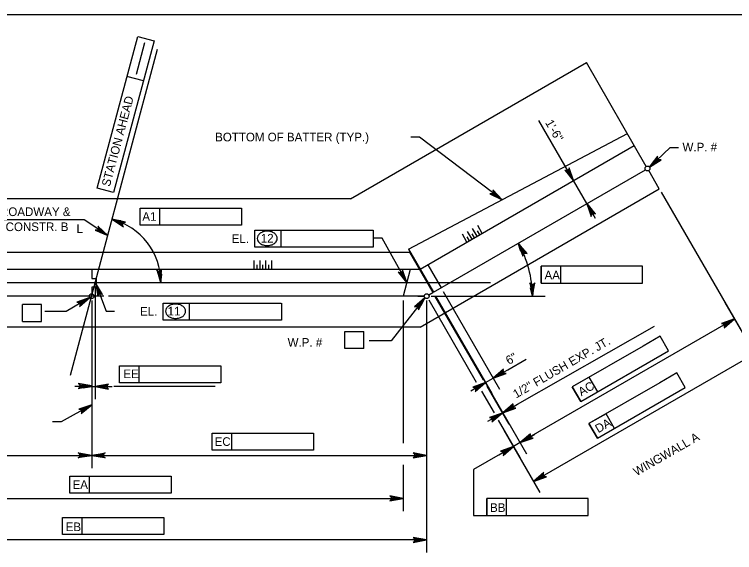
# Model space of a CAD drawing. Extents: x 638255 to 640306, y 296059 to 298435.
# Drawn here: x 638693.7 to 638944.1, y 297045.5 to 297232.5 of the extents above; entities that cross this region are included whole.
import ezdxf

# ---------------------------------------------------------------- set-up
doc = ezdxf.new("R2010")
doc.units = 0
for name, color, linetype in [('2', 7, 'Continuous'), ('Level 10', 7, 'Continuous'), ('Level 11', 7, 'Continuous'), ('Level 2', 7, 'Continuous'), ('Level 3', 7, 'Continuous')]:
    doc.layers.add(name, color=color, linetype=linetype)

msp = doc.modelspace()

# ---------------------------------------------------------------- linework, layer by layer
at = {"layer": '2'}
msp.add_line((638475.46, 297232.46), (639261.46, 297232.46), dxfattribs=at)
at = {"layer": 'Level 10'}
for p, q in [((638810.57, 297168.34), (638892.58, 297215.69)), ((638913.39, 297179.65), (638892.58, 297215.69)), ((638830.74, 297150.88), (638906.81, 297191.04)), ((638834.77, 297143.91), (638909.21, 297186.89)), ((638839.38, 297135.93), (638913.08, 297178.49)), ((638917.91, 297171.82), (638914.24, 297178.18)), ((638834.78, 297123.83), (638917.91, 297171.82)), ((638810.57, 297168.34), (638636.66, 297168.34)), ((638615.29, 297149.79), (638831.04, 297149.87)), ((638830.74, 297150.88), (638839.38, 297135.93)), ((638831.04, 297149.87), (638839.16, 297135.81)), ((638837.43, 297145.44), (638842.04, 297137.47)), ((638834.55, 297143.78), (638611.82, 297143.78)), ((638831.33, 297143.78), (638828.86, 297134.57)), ((638859.26, 297139.18), (638594.57, 297139.18)), ((638724.77, 297134.57), (638610.04, 297134.57)), ((638836.17, 297134.57), (638726.47, 297134.57)), ((638833.95, 297134.57), (638836.17, 297134.57)), ((638837.75, 297135), (638839.16, 297135.81)), ((638834.78, 297123.83), (638615.53, 297123.83))]:
    msp.add_line(p, q, dxfattribs=at)
at = {"layer": 'Level 11'}
msp.add_line((638713.23, 297107.11), (638743.43, 297220.39), dxfattribs=at)
at = {"layer": 'Level 2'}
for p, q in [((638856.37, 297156.38), (638854.79, 297159.11)), ((638852.82, 297154.33), (638851.25, 297157.06)), ((638854.59, 297155.36), (638853.02, 297158.09)), ((638855.48, 297155.87), (638854.67, 297157.27)), ((638851.05, 297153.31), (638849.47, 297156.04)), ((638851.94, 297153.82), (638851.13, 297155.22)), ((638853.71, 297154.84), (638852.9, 297156.25)), ((638777.06, 297143.78), (638777.06, 297146.94)), ((638779.11, 297143.78), (638779.11, 297146.94)), ((638781.15, 297143.78), (638781.15, 297146.94)), ((638783.2, 297143.78), (638783.2, 297146.94)), ((638778.08, 297143.78), (638778.08, 297145.4)), ((638780.13, 297143.78), (638780.13, 297145.4)), ((638782.18, 297143.78), (638782.18, 297145.4))]:
    msp.add_line(p, q, dxfattribs=at)
msp.add_lwpolyline([(638720.59, 297143.78), (638720.59, 297140.71), (638722.12, 297140.71), (638722.12, 297137.64), (638720.59, 297137.64), (638720.59, 297135.6)], dxfattribs=at)
at = {"layer": 'Level 3'}
for p, q in [((638722.47, 297172.11), (638736.59, 297224.82)), ((638736.59, 297224.82), (638742.29, 297223.3)), ((638742.29, 297223.3), (638728.16, 297170.59)), ((638736.14, 297211.74), (638739.07, 297222.66)), ((638738.55, 297209.36), (638732.86, 297210.89)), ((638888.1, 297174.7), (638875.99, 297195.65)), ((638834.54, 297189.85), (638831.55, 297189.85)), ((638863.24, 297168.04), (638834.54, 297189.85)), ((638914.53, 297179.36), (638921.68, 297186.2)), ((638921.68, 297186.2), (638924.63, 297186.2)), ((638892.7, 297166.72), (638888.1, 297174.7)), ((638728.16, 297170.59), (638722.47, 297172.11)), ((638918.6, 297170.64), (638946.21, 297122.8)), ((638892.7, 297166.72), (638895.65, 297161.62)), ((638737.4, 297165.15), (638744.23, 297165.15)), ((638737.4, 297159.26), (638737.4, 297165.15)), ((638744.23, 297159.26), (638744.23, 297165.15)), ((638744.23, 297165.15), (638772.63, 297165.15)), ((638772.63, 297165.15), (638772.63, 297159.26)), ((638717.98, 297161.05), (638683.42, 297161.05)), ((638726.16, 297155.59), (638717.98, 297161.05)), ((638772.63, 297159.26), (638737.4, 297159.26)), ((638777.26, 297157.48), (638786.41, 297157.48)), ((638777.26, 297151.59), (638777.26, 297157.48)), ((638786.41, 297151.59), (638786.41, 297157.48)), ((638786.41, 297157.48), (638818.39, 297157.48)), ((638818.39, 297157.48), (638818.39, 297151.59)), ((638821.56, 297154.7), (638818.62, 297154.7)), ((638830.11, 297139.25), (638821.56, 297154.7)), ((638818.39, 297151.59), (638777.26, 297151.59)), ((638876.81, 297144.93), (638876.81, 297139.03)), ((638905.21, 297144.93), (638876.81, 297144.93)), ((638883.64, 297144.93), (638876.81, 297144.93)), ((638876.81, 297139.03), (638876.81, 297144.93)), ((638883.64, 297139.03), (638883.64, 297144.93)), ((638912.04, 297144.93), (638905.21, 297144.93)), ((638912.04, 297139.03), (638912.04, 297144.93)), ((638721.9, 297139.18), (638725.57, 297129.37)), ((638876.81, 297139.03), (638912.04, 297139.03)), ((638721.83, 297137.64), (638721.83, 297098.72)), ((638719.91, 297134.05), (638711.71, 297129.18)), ((638836.41, 297133.96), (638824.75, 297119.07)), ((638838.55, 297134.57), (638878.2, 297134.57)), ((638839.92, 297134.48), (638856.66, 297105.49)), ((638840.14, 297134.6), (638871.77, 297079.82)), ((638840.14, 297134.6), (638865.77, 297090.23)), ((638840.14, 297134.6), (638859.72, 297100.69)), ((638842.8, 297136.14), (638862.38, 297102.23)), ((638696.52, 297125.74), (638696.52, 297131.64)), ((638703.1, 297131.64), (638696.52, 297131.64)), ((638703.1, 297125.74), (638703.1, 297131.64)), ((638720.59, 297133.04), (638720.59, 297074.8)), ((638745.39, 297126.26), (638745.39, 297132.15)), ((638745.39, 297132.15), (638754.55, 297132.15)), ((638754.55, 297126.26), (638754.55, 297132.15)), ((638754.55, 297132.15), (638786.42, 297132.15)), ((638786.52, 297132.15), (638786.52, 297126.26)), ((638828.91, 297133.04), (638828.91, 297083.47)), ((638837.02, 297133.04), (638837.02, 297074.8)), ((638837.79, 297133.24), (638854.27, 297104.68)), ((638940.68, 297132.38), (638953.19, 297110.73)), ((638711.71, 297129.18), (638704.35, 297129.18)), ((638725.57, 297129.37), (638728.51, 297129.37)), ((638944, 297126.63), (638869.56, 297083.65)), ((638696.52, 297125.74), (638703.1, 297125.74)), ((638786.52, 297126.26), (638745.39, 297126.26)), ((638868.66, 297097), (638916.2, 297124.14)), ((638808.63, 297122.31), (638815.21, 297122.31)), ((638808.63, 297116.42), (638808.63, 297122.31)), ((638815.21, 297116.42), (638815.21, 297122.31)), ((638824.75, 297119.07), (638816.99, 297119.07)), ((638918.18, 297120.65), (638912.26, 297117.23)), ((638921.13, 297115.54), (638918.18, 297120.65)), ((638912.26, 297117.23), (638887.67, 297103.03)), ((638815.21, 297116.42), (638808.63, 297116.42)), ((638950.98, 297114.55), (638874.17, 297070.21)), ((638890.62, 297097.93), (638921.13, 297115.54)), ((638865.27, 297109), (638871.65, 297112.68)), ((638730.22, 297110.38), (638737.05, 297110.38)), ((638730.22, 297104.49), (638730.22, 297110.38)), ((638737.05, 297104.49), (638737.05, 297110.38)), ((638737.05, 297110.38), (638765.45, 297110.38)), ((638765.45, 297110.38), (638765.45, 297104.49)), ((638862.72, 297107.53), (638865.27, 297109)), ((638893.58, 297106.45), (638887.67, 297103.03)), ((638896.53, 297101.34), (638893.58, 297106.45)), ((638923.97, 297107.89), (638918.06, 297104.48)), ((638926.92, 297102.79), (638923.97, 297107.89)), ((638765.45, 297104.49), (638730.22, 297104.49)), ((638857.51, 297104.52), (638860.17, 297106.06)), ((638918.06, 297104.48), (638893.46, 297090.28)), ((638717.64, 297103.14), (638714.7, 297103.14)), ((638720.59, 297103.14), (638721.83, 297103.14)), ((638724.77, 297103.14), (638727.72, 297103.14)), ((638763.49, 297103.14), (638728.24, 297103.14)), ((638854.96, 297103.05), (638852.41, 297101.57)), ((638856.06, 297101.59), (638860.45, 297093.99)), ((638857.92, 297103.3), (638865.54, 297090.1)), ((638887.67, 297103.03), (638890.62, 297097.93)), ((638890.61, 297097.93), (638887.67, 297103.03)), ((638896.41, 297085.17), (638926.92, 297102.79)), ((638720.59, 297096.82), (638709.96, 297090.87)), ((638866.11, 297095.53), (638868.66, 297097)), ((638837.02, 297094.09), (638837.02, 297045.45)), ((638863.33, 297093.93), (638863.55, 297094.06)), ((638860.78, 297092.45), (638858.23, 297090.98)), ((638861.89, 297091.5), (638869.41, 297078.46)), ((638899.38, 297093.69), (638893.46, 297090.28)), ((638902.32, 297088.59), (638899.38, 297093.69)), ((638709.96, 297090.87), (638707.01, 297090.87)), ((638893.46, 297090.28), (638896.41, 297085.17)), ((638896.41, 297085.17), (638893.46, 297090.28)), ((638762.5, 297086.94), (638769.33, 297086.94)), ((638762.5, 297081.05), (638762.5, 297086.94)), ((638769.33, 297081.05), (638769.33, 297086.94)), ((638769.33, 297086.94), (638797.73, 297086.94)), ((638797.73, 297086.94), (638797.73, 297081.05)), ((638863.89, 297088.04), (638876.38, 297066.39)), ((638872.11, 297085.12), (638874.67, 297086.6)), ((638867.2, 297082.29), (638853.36, 297074.3)), ((638869.56, 297083.65), (638867.2, 297082.29)), ((638609.2, 297079.23), (638720.59, 297079.23)), ((638720.59, 297079.23), (638837.02, 297079.23)), ((638797.73, 297081.05), (638762.5, 297081.05)), ((638864.65, 297080.81), (638862.1, 297079.34)), ((638828.91, 297076), (638828.91, 297059.84)), ((638853.36, 297074.3), (638853.36, 297058.37)), ((638712.98, 297071.98), (638719.81, 297071.98)), ((638712.98, 297066.08), (638712.98, 297071.98)), ((638719.81, 297066.08), (638719.81, 297071.98)), ((638719.81, 297071.98), (638748.21, 297071.98)), ((638748.21, 297071.98), (638748.21, 297066.08)), ((638612.27, 297064.26), (638828.91, 297064.26)), ((638748.21, 297066.08), (638712.98, 297066.08)), ((638857.96, 297064.27), (638857.96, 297058.37)), ((638886.36, 297064.27), (638857.96, 297064.27)), ((638864.79, 297064.27), (638857.96, 297064.27)), ((638857.96, 297058.37), (638857.96, 297064.27)), ((638864.79, 297058.37), (638864.79, 297064.27)), ((638893.19, 297064.27), (638886.36, 297064.27)), ((638893.19, 297058.37), (638893.19, 297064.27)), ((638710.46, 297057.59), (638717.29, 297057.59)), ((638710.46, 297051.7), (638710.46, 297057.59)), ((638717.29, 297051.7), (638717.29, 297057.59)), ((638717.29, 297057.59), (638745.7, 297057.59)), ((638745.7, 297057.59), (638745.7, 297051.7)), ((638853.36, 297058.37), (638857.96, 297058.37)), ((638857.96, 297058.37), (638893.19, 297058.37)), ((638745.7, 297051.7), (638710.46, 297051.7)), ((638837.02, 297049.88), (638609.2, 297049.88))]:
    msp.add_line(p, q, dxfattribs=at)
for points in [[(638914.53, 297179.36), (638918.5, 297181.95), (638918.07, 297181.88), (638917.72, 297181.98), (638917.46, 297182.16), (638917.29, 297182.43), (638917.2, 297182.78), (638917.29, 297183.21), (638914.53, 297179.36), (638917.2, 297182.78), (638917.29, 297182.43), (638914.53, 297179.36), (638917.46, 297182.16), (638917.72, 297181.98), (638914.53, 297179.36), (638918.07, 297181.88)], [(638888.1, 297174.7), (638886.53, 297179.16), (638886.49, 297178.73), (638886.31, 297178.41), (638886.07, 297178.21), (638885.77, 297178.1), (638885.41, 297178.1), (638885.01, 297178.29), (638888.1, 297174.7), (638885.41, 297178.1), (638885.77, 297178.1), (638888.1, 297174.7), (638886.07, 297178.21), (638886.31, 297178.41), (638888.1, 297174.7), (638886.49, 297178.73)], [(638863.24, 297168.04), (638860.07, 297171.55), (638860.2, 297171.14), (638860.16, 297170.78), (638860.01, 297170.5), (638859.78, 297170.28), (638859.45, 297170.14), (638859.01, 297170.16), (638863.24, 297168.04), (638859.45, 297170.14), (638859.78, 297170.28), (638863.24, 297168.04), (638860.01, 297170.5), (638860.16, 297170.78), (638863.24, 297168.04), (638860.2, 297171.14)], [(638892.7, 297166.72), (638894.27, 297162.26), (638894.31, 297162.69), (638894.49, 297163.01), (638894.73, 297163.21), (638895.03, 297163.32), (638895.39, 297163.32), (638895.78, 297163.13), (638892.7, 297166.72), (638895.39, 297163.32), (638895.03, 297163.32), (638892.7, 297166.72), (638894.73, 297163.21), (638894.49, 297163.01), (638892.7, 297166.72), (638894.31, 297162.69)], [(638727.68, 297161.27), (638731.63, 297158.67), (638731.4, 297159.04), (638731.35, 297159.4), (638731.42, 297159.71), (638731.59, 297159.97), (638731.88, 297160.19), (638732.31, 297160.28), (638727.68, 297161.27), (638731.88, 297160.19), (638731.59, 297159.97), (638727.68, 297161.27), (638731.42, 297159.71), (638731.35, 297159.4), (638727.68, 297161.27), (638731.4, 297159.04)], [(638726.16, 297155.59), (638722.77, 297158.9), (638722.93, 297158.49), (638722.91, 297158.13), (638722.79, 297157.84), (638722.57, 297157.61), (638722.24, 297157.46), (638721.8, 297157.45), (638726.16, 297155.59), (638722.24, 297157.46), (638722.57, 297157.61), (638726.16, 297155.59), (638722.79, 297157.84), (638722.91, 297158.13), (638726.16, 297155.59), (638722.93, 297158.49)], [(638868.86, 297152.96), (638870.43, 297148.49), (638870.46, 297148.93), (638870.64, 297149.24), (638870.88, 297149.44), (638871.18, 297149.55), (638871.54, 297149.55), (638871.94, 297149.36), (638868.86, 297152.96), (638871.54, 297149.55), (638871.18, 297149.55), (638868.86, 297152.96), (638870.88, 297149.44), (638870.64, 297149.24), (638868.86, 297152.96), (638870.46, 297148.93)], [(638744.68, 297139.16), (638744.9, 297143.89), (638744.71, 297143.5), (638744.42, 297143.27), (638744.12, 297143.17), (638743.8, 297143.18), (638743.47, 297143.33), (638743.18, 297143.65), (638744.68, 297139.16), (638743.47, 297143.33), (638743.8, 297143.18), (638744.68, 297139.16), (638744.12, 297143.17), (638744.42, 297143.27), (638744.68, 297139.16), (638744.71, 297143.5)], [(638830.11, 297139.25), (638828.62, 297143.74), (638828.58, 297143.31), (638828.4, 297142.99), (638828.15, 297142.79), (638827.85, 297142.69), (638827.49, 297142.7), (638827.1, 297142.89), (638830.11, 297139.25), (638827.49, 297142.7), (638827.85, 297142.69), (638830.11, 297139.25), (638828.15, 297142.79), (638828.4, 297142.99), (638830.11, 297139.25), (638828.58, 297143.31)], [(638721.9, 297139.18), (638722.71, 297134.51), (638722.82, 297134.94), (638723.05, 297135.22), (638723.32, 297135.38), (638723.63, 297135.44), (638723.99, 297135.37), (638724.35, 297135.12), (638721.9, 297139.18), (638723.99, 297135.37), (638723.63, 297135.44), (638721.9, 297139.18), (638723.32, 297135.38), (638723.05, 297135.22), (638721.9, 297139.18), (638722.82, 297134.94)], [(638873.78, 297134.57), (638874.66, 297139.22), (638874.41, 297138.86), (638874.1, 297138.68), (638873.78, 297138.63), (638873.47, 297138.68), (638873.16, 297138.86), (638872.91, 297139.22), (638873.78, 297134.57), (638873.16, 297138.86), (638873.47, 297138.68), (638873.78, 297134.57), (638873.78, 297138.63), (638874.1, 297138.68), (638873.78, 297134.57), (638874.41, 297138.86)], [(638719.91, 297134.05), (638715.47, 297132.43), (638715.9, 297132.39), (638716.22, 297132.22), (638716.43, 297131.98), (638716.54, 297131.68), (638716.54, 297131.32), (638716.36, 297130.92), (638719.91, 297134.05), (638716.54, 297131.32), (638716.54, 297131.68), (638719.91, 297134.05), (638716.43, 297131.98), (638716.22, 297132.22), (638719.91, 297134.05), (638715.9, 297132.39)], [(638836.41, 297133.96), (638832.86, 297130.84), (638833.28, 297130.97), (638833.63, 297130.92), (638833.91, 297130.77), (638834.13, 297130.54), (638834.26, 297130.2), (638834.23, 297129.76), (638836.41, 297133.96), (638834.26, 297130.2), (638834.13, 297130.54), (638836.41, 297133.96), (638833.91, 297130.77), (638833.63, 297130.92), (638836.41, 297133.96), (638833.28, 297130.97)], [(638944, 297126.63), (638939.54, 297125.06), (638939.97, 297125.02), (638940.29, 297124.84), (638940.49, 297124.6), (638940.6, 297124.3), (638940.6, 297123.94), (638940.41, 297123.55), (638944, 297126.63), (638940.6, 297123.94), (638940.6, 297124.3), (638944, 297126.63), (638940.49, 297124.6), (638940.29, 297124.84), (638944, 297126.63), (638939.97, 297125.02)], [(638860.17, 297106.06), (638864.64, 297107.63), (638864.2, 297107.66), (638863.89, 297107.84), (638863.68, 297108.08), (638863.57, 297108.38), (638863.58, 297108.74), (638863.76, 297109.14), (638860.17, 297106.06), (638863.58, 297108.74), (638863.57, 297108.38), (638860.17, 297106.06), (638863.68, 297108.08), (638863.89, 297107.84), (638860.17, 297106.06), (638864.2, 297107.66)], [(638720.59, 297103.34), (638715.94, 297104.22), (638716.3, 297103.97), (638716.48, 297103.66), (638716.54, 297103.34), (638716.48, 297103.03), (638716.3, 297102.72), (638715.94, 297102.47), (638720.59, 297103.34), (638716.3, 297102.72), (638716.48, 297103.03), (638720.59, 297103.34), (638716.54, 297103.34), (638716.48, 297103.66), (638720.59, 297103.34), (638716.3, 297103.97)], [(638721.83, 297103.14), (638726.48, 297102.27), (638726.12, 297102.51), (638725.93, 297102.83), (638725.88, 297103.14), (638725.93, 297103.45), (638726.12, 297103.76), (638726.48, 297104.01), (638721.83, 297103.14), (638726.12, 297103.76), (638725.93, 297103.45), (638721.83, 297103.14), (638725.88, 297103.14), (638725.93, 297102.83), (638721.83, 297103.14), (638726.12, 297102.51)], [(638857.51, 297104.52), (638853.05, 297102.95), (638853.48, 297102.92), (638853.8, 297102.74), (638854, 297102.49), (638854.11, 297102.2), (638854.11, 297101.83), (638853.92, 297101.44), (638857.51, 297104.52), (638854.11, 297101.83), (638854.11, 297102.2), (638857.51, 297104.52), (638854, 297102.49), (638853.8, 297102.74), (638857.51, 297104.52), (638853.48, 297102.92)], [(638720.59, 297096.82), (638716.11, 297095.31), (638716.54, 297095.27), (638716.85, 297095.09), (638717.05, 297094.84), (638717.16, 297094.54), (638717.15, 297094.18), (638716.96, 297093.79), (638720.59, 297096.82), (638717.15, 297094.18), (638717.16, 297094.54), (638720.59, 297096.82), (638717.05, 297094.84), (638716.85, 297095.09), (638720.59, 297096.82), (638716.54, 297095.27)], [(638863.55, 297094.06), (638868.02, 297095.63), (638867.58, 297095.66), (638867.27, 297095.84), (638867.07, 297096.08), (638866.96, 297096.38), (638866.96, 297096.74), (638867.15, 297097.14), (638863.55, 297094.06), (638866.96, 297096.74), (638866.96, 297096.38), (638863.55, 297094.06), (638867.07, 297096.08), (638867.27, 297095.84), (638863.55, 297094.06), (638867.58, 297095.66)], [(638863.33, 297093.93), (638858.87, 297092.36), (638859.3, 297092.32), (638859.62, 297092.14), (638859.82, 297091.9), (638859.93, 297091.6), (638859.93, 297091.24), (638859.74, 297090.85), (638863.33, 297093.93), (638859.93, 297091.24), (638859.93, 297091.6), (638863.33, 297093.93), (638859.82, 297091.9), (638859.62, 297092.14), (638863.33, 297093.93), (638859.3, 297092.32)], [(638869.56, 297083.65), (638874.03, 297085.22), (638873.59, 297085.26), (638873.28, 297085.43), (638873.07, 297085.68), (638872.96, 297085.97), (638872.97, 297086.33), (638873.16, 297086.73), (638869.56, 297083.65), (638872.97, 297086.33), (638872.96, 297085.97), (638869.56, 297083.65), (638873.07, 297085.68), (638873.28, 297085.43), (638869.56, 297083.65), (638873.59, 297085.26)], [(638867.2, 297082.29), (638862.74, 297080.72), (638863.17, 297080.68), (638863.49, 297080.5), (638863.69, 297080.26), (638863.8, 297079.96), (638863.8, 297079.6), (638863.61, 297079.2), (638867.2, 297082.29), (638863.8, 297079.6), (638863.8, 297079.96), (638867.2, 297082.29), (638863.69, 297080.26), (638863.49, 297080.5), (638867.2, 297082.29), (638863.17, 297080.68)], [(638720.59, 297079.23), (638715.94, 297078.35), (638716.12, 297078.48), (638716.3, 297078.6), (638716.39, 297078.76), (638716.48, 297078.91), (638716.51, 297079.07), (638716.54, 297079.23), (638716.51, 297079.38), (638716.48, 297079.54), (638716.39, 297079.69), (638716.3, 297079.85), (638716.12, 297079.97), (638715.94, 297080.1), (638720.59, 297079.23), (638716.12, 297079.97), (638716.3, 297079.85), (638720.59, 297079.23), (638716.39, 297079.69), (638716.48, 297079.54), (638720.59, 297079.23), (638716.51, 297079.38), (638716.54, 297079.23), (638720.59, 297079.23), (638716.51, 297079.07), (638716.48, 297078.91), (638720.59, 297079.23), (638716.39, 297078.76), (638716.3, 297078.6), (638720.59, 297079.23), (638716.12, 297078.48)], [(638720.59, 297079.23), (638725.24, 297080.1), (638725.06, 297079.97), (638724.88, 297079.85), (638724.79, 297079.69), (638724.7, 297079.54), (638724.67, 297079.38), (638724.65, 297079.23), (638724.67, 297079.07), (638724.7, 297078.91), (638724.79, 297078.76), (638724.88, 297078.6), (638725.06, 297078.48), (638725.24, 297078.35), (638720.59, 297079.23), (638725.06, 297078.48), (638724.88, 297078.6), (638720.59, 297079.23), (638724.79, 297078.76), (638724.7, 297078.91), (638720.59, 297079.23), (638724.67, 297079.07), (638724.65, 297079.23), (638720.59, 297079.23), (638724.67, 297079.38), (638724.7, 297079.54), (638720.59, 297079.23), (638724.79, 297079.69), (638724.88, 297079.85), (638720.59, 297079.23), (638725.06, 297079.97)], [(638837.02, 297079.23), (638832.37, 297080.1), (638832.72, 297079.85), (638832.91, 297079.54), (638832.96, 297079.23), (638832.91, 297078.91), (638832.72, 297078.6), (638832.37, 297078.35), (638837.02, 297079.23), (638832.72, 297078.6), (638832.91, 297078.91), (638837.02, 297079.23), (638832.96, 297079.23), (638832.91, 297079.54), (638837.02, 297079.23), (638832.72, 297079.85)], [(638874.17, 297070.21), (638878.64, 297071.78), (638878.2, 297071.82), (638877.89, 297072), (638877.69, 297072.24), (638877.58, 297072.54), (638877.58, 297072.9), (638877.77, 297073.3), (638874.17, 297070.21), (638877.58, 297072.9), (638877.58, 297072.54), (638874.17, 297070.21), (638877.69, 297072.24), (638877.89, 297072), (638874.17, 297070.21), (638878.2, 297071.82)], [(638828.91, 297064.26), (638824.26, 297065.13), (638824.62, 297064.89), (638824.81, 297064.57), (638824.86, 297064.26), (638824.81, 297063.95), (638824.62, 297063.64), (638824.26, 297063.39), (638828.91, 297064.26), (638824.62, 297063.64), (638824.81, 297063.95), (638828.91, 297064.26), (638824.86, 297064.26), (638824.81, 297064.57), (638828.91, 297064.26), (638824.62, 297064.89)], [(638837.02, 297049.88), (638832.37, 297050.75), (638832.72, 297050.5), (638832.91, 297050.19), (638832.96, 297049.88), (638832.91, 297049.56), (638832.72, 297049.25), (638832.37, 297049), (638837.02, 297049.88), (638832.72, 297049.25), (638832.91, 297049.56), (638837.02, 297049.88), (638832.96, 297049.88), (638832.91, 297050.19), (638837.02, 297049.88), (638832.72, 297050.5)]]:
    msp.add_lwpolyline(points, dxfattribs=at)
for points in [[(638916.33, 297181.76), (638917, 297181.05), (638914.54, 297179.36)], [(638887.05, 297177.49), (638886.2, 297177), (638888.1, 297174.7)], [(638860.35, 297169.61), (638860.95, 297170.41), (638863.04, 297168.2)], [(638894.6, 297164.41), (638893.75, 297163.92), (638892.7, 297166.72)], [(638730.37, 297159.84), (638730.69, 297160.77), (638727.74, 297161.25)], [(638723.98, 297157.63), (638723.44, 297156.82), (638726.16, 297155.59)], [(638870.66, 297150.57), (638869.79, 297150.12), (638868.86, 297152.95)], [(638744.98, 297142.15), (638744, 297142.08), (638744.68, 297139.18)], [(638829.15, 297141.99), (638828.29, 297141.52), (638830.15, 297139.18)], [(638722.47, 297136.26), (638723.38, 297136.63), (638721.83, 297139.18)], [(638873.17, 297137.5), (638874.16, 297137.54), (638873.78, 297134.57)], [(638717.13, 297132.97), (638717.64, 297132.12), (638719.92, 297134.05)], [(638834.99, 297131.35), (638834.22, 297131.95), (638836.42, 297133.97)], [(638941.21, 297125.58), (638941.7, 297124.73), (638944, 297126.63)], [(638862.48, 297107.95), (638862.97, 297107.1), (638860.17, 297106.06)], [(638854.71, 297103.47), (638855.21, 297102.62), (638857.51, 297104.52)], [(638717.64, 297103.63), (638717.64, 297102.65), (638720.59, 297103.14)], [(638724.77, 297103.63), (638724.77, 297102.65), (638721.83, 297103.14)], [(638718.01, 297094.82), (638717.55, 297095.68), (638720.39, 297096.63)], [(638860.54, 297092.88), (638861.03, 297092.03), (638863.33, 297093.93)], [(638865.86, 297095.95), (638866.35, 297095.1), (638863.55, 297094.06)], [(638871.87, 297085.55), (638872.36, 297084.7), (638869.56, 297083.65)], [(638864.41, 297081.24), (638864.9, 297080.39), (638867.2, 297082.29)], [(638834.07, 297079.72), (638834.07, 297078.73), (638837.02, 297079.23)], [(638876.48, 297072.11), (638876.97, 297071.26), (638874.17, 297070.21)], [(638825.97, 297064.75), (638825.97, 297063.77), (638828.91, 297064.26)], [(638834.07, 297050.37), (638834.07, 297049.38), (638837.02, 297049.88)]]:
    msp.add_lwpolyline(points, close=True, dxfattribs=at)
for centre in [(638913.82, 297178.91), (638720.59, 297134.57), (638837.02, 297134.57)]:
    msp.add_circle(centre, 0.849, dxfattribs=at)
for centre, radius, start, end in [((638721.82, 297139.18), 22.86, 359.9991, 75.1795), ((638781.29, 297153.45), 3.65, 106.5358, 125.6316), ((638781.63, 297152.29), 4.86, 90, 106.5358), ((638781.63, 297152.29), 4.86, 73.4642, 90), ((638781.97, 297153.45), 3.65, 54.3684, 73.4642), ((638779.96, 297154.64), 1.82, 149.9767, 180), ((638779.96, 297154.64), 1.82, 180, 210.0233), ((638780.76, 297154.18), 2.75, 125.6316, 149.9767), ((638782.5, 297154.18), 2.75, 30.0233, 54.3684), ((638783.3, 297154.64), 1.82, 0, 30.0233), ((638783.3, 297154.64), 1.82, 329.9767, 0), ((638780.76, 297155.11), 2.75, 210.0233, 234.3684), ((638781.29, 297155.84), 3.65, 234.3684, 253.4642), ((638781.63, 297157), 4.86, 253.4642, 270), ((638781.63, 297157), 4.86, 270, 286.5358), ((638781.97, 297155.84), 3.65, 286.5358, 305.6316), ((638782.5, 297155.11), 2.75, 305.6316, 329.9767), ((638837.02, 297134.57), 36.77, 360, 30.0012), ((638837.02, 297134.57), 36.77, 4.5939, 5.05), ((638749.42, 297128.11), 3.65, 106.5358, 125.6316), ((638749.76, 297126.95), 4.86, 90, 106.5358), ((638749.76, 297126.95), 4.86, 73.4642, 90), ((638750.1, 297128.11), 3.65, 54.3684, 73.4642), ((638748.09, 297129.31), 1.82, 149.9767, 180), ((638748.09, 297129.31), 1.82, 180, 210.0233), ((638748.89, 297128.85), 2.75, 125.6316, 149.9767), ((638750.63, 297128.85), 2.75, 30.0233, 54.3684), ((638751.43, 297129.31), 1.82, 0, 30.0233), ((638751.43, 297129.31), 1.82, 329.9767, 0), ((638748.89, 297129.77), 2.75, 210.0233, 234.3684), ((638749.42, 297130.51), 3.65, 234.3684, 253.4642), ((638749.76, 297131.67), 4.86, 253.4642, 270), ((638749.76, 297131.67), 4.86, 270, 286.5358), ((638750.1, 297130.51), 3.65, 286.5358, 305.6316), ((638750.63, 297129.77), 2.75, 305.6316, 329.9767)]:
    msp.add_arc(centre, radius, start, end, dxfattribs=at)

# ---------------------------------------------------------------- texts
for s, height, rotation, p in [('STATION AHEAD', 3.0001, 75, (638726.88, 297172.41)), ('1\'-6"', 3, 299.9871, (638878.13, 297194.84)), ('1/2" FLUSH EXP. JT.', 3.0001, 30.0203, (638868.12, 297098.96)), ('6"', 3, 30.0203, (638865.6, 297110.62)), ('AC', 3, 30, (638890.8, 297099.73)), ('DA', 3, 29.9995, (638896.69, 297086.89)), ('WINGWALL A', 3, 29.9995, (638909.96, 297071.95))]:
    msp.add_text(s, height=height, rotation=rotation, dxfattribs=at).set_placement(p)
for s, height, p in [('BOTTOM OF BATTER (TYP.)', 3.0001, (638763.5, 297188.34)), ('W.P. # ', 3, (638925.96, 297184.85)), ('C ROADWAY &', 3.0001, (638684.71, 297162.39)), ('A1', 3, (638738.19, 297160.74)), ('CONSTR. B', 3, (638690.67, 297157.17)), ('L', 3, (638715.31, 297156.48)), ('EL.', 3, (638769.26, 297153.07)), ('12', 3, (638779.36, 297153.18)), ('AA', 3, (638878.01, 297140.38)), ('EL.', 3, (638737.39, 297127.74)), ('11', 3, (638746.97, 297127.85)), ('W.P. # ', 3, (638788.7, 297117)), ('EE', 3, (638731.61, 297106.07)), ('EC', 3, (638763.32, 297082.53)), ('EA', 3, (638713.94, 297067.57)), ('BB', 3, (638859.07, 297059.58)), ('EB', 3, (638711.55, 297052.91))]:
    msp.add_text(s, height=height, dxfattribs=at).set_placement(p)

doc.saveas('drawing.dxf')
